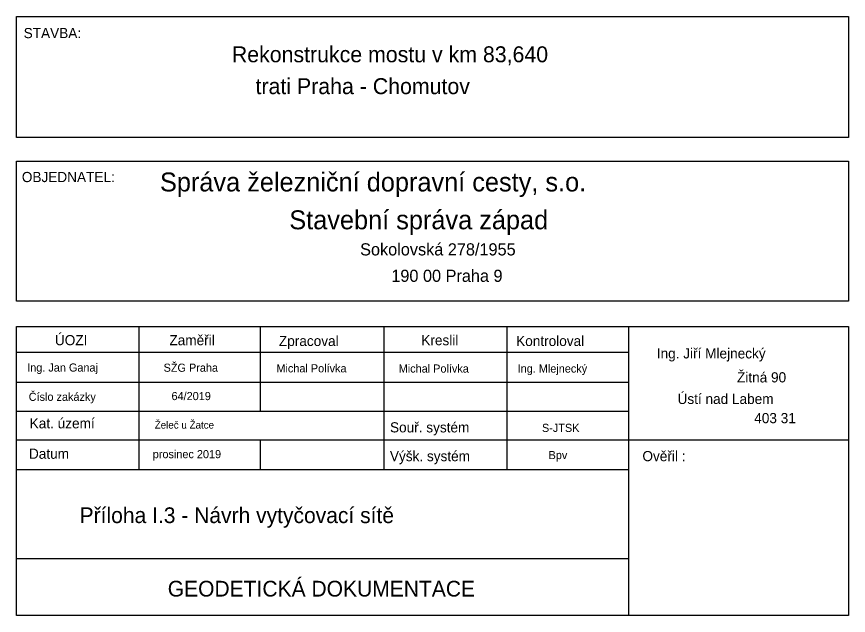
# Model space of a CAD drawing. Extents: x -879530 to -879371, y -1019242 to -1019127.
import ezdxf

# ---------------------------------------------------------------- set-up
doc = ezdxf.new("R2010")
doc.units = 0
doc.layers.add('LEGENDA', color=7, linetype='Continuous')
doc.layers.add('tabulka', color=7, linetype='Continuous')

msp = doc.modelspace()

# ---------------------------------------------------------------- linework, layer by layer
at = {"layer": 'tabulka'}
for p, q in [((-879530.09, -1019186.45), (-879371.44, -1019186.45)), ((-879506.8, -1019186.45), (-879506.8, -1019213.77)), ((-879483.66, -1019186.45), (-879483.66, -1019202.65)), ((-879460.06, -1019186.45), (-879460.06, -1019213.77)), ((-879436.61, -1019186.45), (-879436.61, -1019213.77)), ((-879413.31, -1019241.58), (-879413.31, -1019186.45)), ((-879530.09, -1019191.36), (-879413.31, -1019191.36)), ((-879530.09, -1019197.07), (-879413.31, -1019197.07)), ((-879530.09, -1019202.65), (-879413.31, -1019202.65)), ((-879530.09, -1019208.07), (-879371.44, -1019208.07)), ((-879483.66, -1019208.07), (-879483.66, -1019213.77)), ((-879530.09, -1019213.77), (-879413.31, -1019213.77)), ((-879530.09, -1019230.76), (-879413.31, -1019230.76))]:
    msp.add_line(p, q, dxfattribs=at)
for points in [[(-879530.09, -1019127.36), (-879371.44, -1019127.36), (-879371.44, -1019150.43), (-879530.09, -1019150.43)], [(-879530.09, -1019154.95), (-879371.44, -1019154.95), (-879371.44, -1019181.64), (-879530.09, -1019181.64)]]:
    msp.add_lwpolyline(points, close=True, dxfattribs=at)
msp.add_lwpolyline([(-879371.44, -1019186.45), (-879371.44, -1019241.58), (-879530.09, -1019241.58), (-879530.09, -1019186.45)], dxfattribs=at)

# ---------------------------------------------------------------- texts
at = {"layer": 'LEGENDA'}
for s, p in [('Rekonstrukce mostu v km 83,640 ', (-879489.04, -1019136.07)), ('    trati Praha - Chomutov', (-879489.04, -1019142.15))]:
    msp.add_text(s, height=3.04, dxfattribs=at).set_placement(p)
at = {"layer": 'tabulka'}
for s, height, p in [('STAVBA:', 1.94, (-879528.75, -1019131.47)), ('OBJEDNATEL:', 1.94, (-879529.1, -1019158.93)), ('Správa železniční dopravní cesty, s.o.', 3.61, (-879502.75, -1019160.71)), ('Stavební správa západ', 3.61, (-879478.08, -1019167.93)), ('Sokolovská 278/1955', 2.32, (-879464.57, -1019172.92)), ('190 00 Praha 9', 2.32, (-879458.62, -1019177.96)), ('ÚOZI', 1.94, (-879522.79, -1019190.05)), ('Zaměřil', 1.94, (-879500.95, -1019190.05)), ('Zpracoval', 1.94, (-879480.06, -1019190.2)), ('Kreslil', 1.94, (-879452.9, -1019190.05)), ('Kontroloval', 1.94, (-879434.81, -1019190.2)), ('Ing. Jiří Mlejnecký', 1.94, (-879407.98, -1019192.57)), ('Ing. Jan Ganaj', 1.552, (-879528.08, -1019195.08)), ('SŽG Praha', 1.552, (-879502.06, -1019195.11)), ('Michal Polívka', 1.552, (-879480.54, -1019195.23)), ('Michal Polívka', 1.552, (-879457.21, -1019195.27)), ('Ing. Mlejnecký', 1.552, (-879434.52, -1019195.27)), ('Žitná 90', 1.94, (-879392.68, -1019197.14)), ('Číslo zakázky', 1.552, (-879527.79, -1019200.66)), ('64/2019', 1.552, (-879500.55, -1019200.52)), ('Ústí nad Labem', 1.94, (-879404.02, -1019201.26)), ('403 31', 1.94, (-879389.39, -1019204.92)), ('Kat. území', 1.94, (-879527.6, -1019205.91)), ('Želeč u Žatce', 1.3968, (-879503.75, -1019205.95)), ('Souř. systém', 1.94, (-879458.87, -1019206.68)), ('S-JTSK', 1.552, (-879429.88, -1019206.59)), ('Datum', 1.94, (-879527.74, -1019211.71)), ('prosinec 2019', 1.552, (-879504.13, -1019211.6)), ('Výšk. systém', 1.94, (-879458.89, -1019212.17)), ('Bpv', 1.552, (-879428.62, -1019211.78)), ('Ověřil :', 1.94, (-879410.72, -1019212.17)), ('Příloha I.3 - Návrh vytyčovací sítě', 3, (-879518.08, -1019223.98)), ('GEODETICKÁ DOKUMENTACE ', 3, (-879501.27, -1019237.99))]:
    msp.add_text(s, height=height, dxfattribs=at).set_placement(p)

doc.saveas('drawing.dxf')
